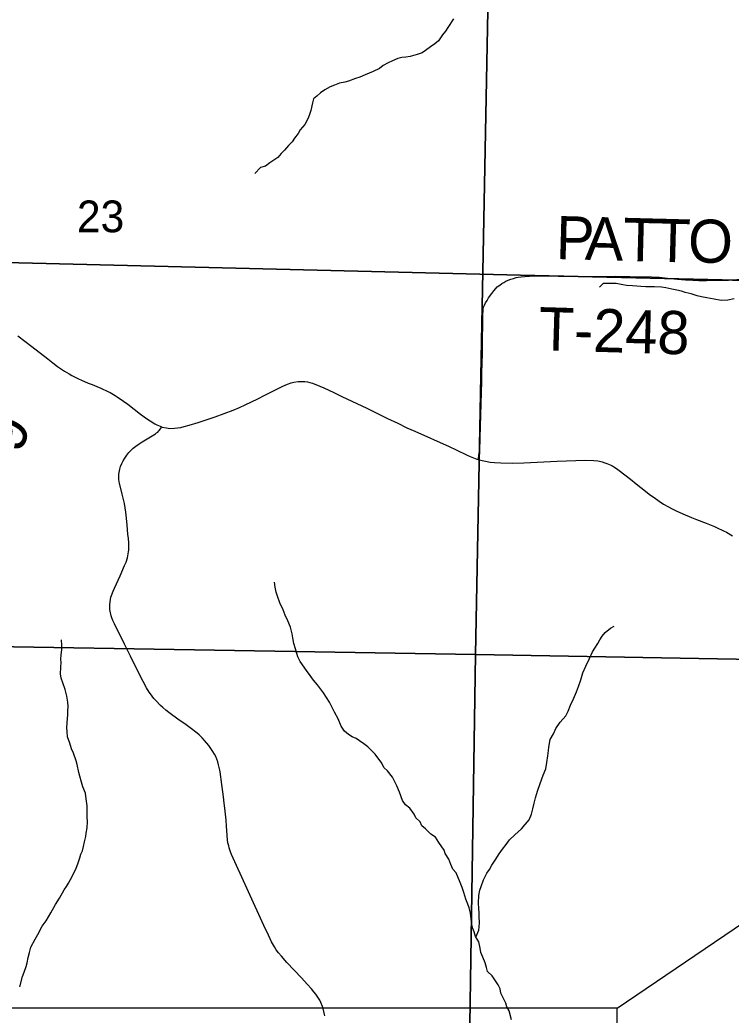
# Model space of a CAD drawing. Extents: x 0 to 34, y 0 to 22.
# Drawn here: x 11.845 to 12.781, y 16.534 to 17.845 of the extents above; entities that cross this region are included whole.
import ezdxf

# ---------------------------------------------------------------- set-up
doc = ezdxf.new("R2010")
doc.units = 0
for name, color, linetype in [('GM_X_Corporation', 7, 'Continuous'), ('GM_X_County_Road', 7, 'Continuous'), ('GM_X_Minor_River', 7, 'Continuous'), ('GM_X_Section_Text', 7, 'Continuous'), ('GM_X_Township_Road', 7, 'Continuous'), ('GM_X_Township_Road_Text', 7, 'Continuous'), ('SH_Text', 7, 'Continuous')]:
    doc.layers.add(name, color=color, linetype=linetype)

msp = doc.modelspace()

# ---------------------------------------------------------------- linework, layer by layer
at = {"layer": 'GM_X_Corporation'}
for points in [[(16.7661, 20.4), (11.5001, 20.4), (11.498, 20.2911), (11.486, 19.6423), (11.4741, 19.003), (11.4514, 17.7789), (11.4477, 17.5329), (11.8073, 17.526), (12.504, 17.5091), (12.7693, 17.5027), (12.7967, 17.502), (13.2742, 17.4966), (14.0954, 17.4811)], [(14.0954, 17.4811), (13.2742, 17.4966), (12.7967, 17.502), (12.7693, 17.5027), (12.504, 17.5091), (11.8073, 17.526), (11.4477, 17.5329), (11.0329, 17.5442), (10.9447, 17.5459), (10.9437, 17.4908), (10.9418, 17.3896), (10.9206, 16.4568), (10.9139, 16.0819), (10.9086, 15.7107), (10.9052, 15.3502), (10.897, 14.5214)]]:
    msp.add_lwpolyline(points, dxfattribs=at)
for points in [[(11.4565, 18.0343), (12.4638, 18.0185), (12.4446, 17.0089), (11.4395, 17.0255)], [(12.4638, 18.0185), (13.4723, 18.0001), (13.4493, 16.9912), (12.4446, 17.0089)], [(11.4395, 17.0255), (12.4446, 17.0089), (12.4291, 16.0062), (11.4274, 16.0262)], [(12.4446, 17.0089), (13.4493, 16.9912), (13.4336, 15.974), (12.4291, 16.0062)]]:
    msp.add_lwpolyline(points, close=True, dxfattribs=at)
at = {"layer": 'GM_X_County_Road'}
msp.add_lwpolyline([(11.8419, 17.429), (11.8603, 17.4148), (11.8813, 17.3985), (11.888, 17.3933), (11.8942, 17.3887), (11.9034, 17.3825), (11.9094, 17.3788), (11.9129, 17.3767), (11.9219, 17.3721), (11.9256, 17.3703), (11.9346, 17.3666), (11.9398, 17.3646), (11.9461, 17.362), (11.9512, 17.3598), (11.9603, 17.3557), (11.9634, 17.3541), (11.97, 17.3504), (11.9729, 17.3486), (11.9809, 17.343), (11.987, 17.3387), (11.9951, 17.3325), (12.0033, 17.3257), (12.0113, 17.32), (12.0161, 17.3169), (12.0225, 17.313), (12.025, 17.3116), (12.0295, 17.3097), (12.0311, 17.3092), (12.0321, 17.3088), (12.0376, 17.3076), (12.04, 17.3072), (12.0423, 17.307), (12.0482, 17.3072), (12.0521, 17.3075), (12.0567, 17.3083), (12.0612, 17.3093), (12.0677, 17.3111), (12.0796, 17.3147), (12.0885, 17.3176), (12.1019, 17.3224), (12.1255, 17.3312), (12.1339, 17.3345), (12.1413, 17.3378), (12.158, 17.3458), (12.1664, 17.3501), (12.1908, 17.3624), (12.1969, 17.3652), (12.2019, 17.3668), (12.2053, 17.3678), (12.2109, 17.3687), (12.2131, 17.3689), (12.22, 17.3687), (12.2233, 17.3682), (12.2264, 17.3675), (12.2298, 17.3664), (12.2395, 17.3627), (12.2447, 17.3605), (12.2579, 17.3543), (12.2688, 17.3492), (12.3017, 17.3335), (12.3146, 17.3272), (12.3289, 17.3202), (12.3422, 17.3137), (12.3543, 17.3079), (12.3648, 17.3032), (12.41, 17.2829), (12.419, 17.2786), (12.4337, 17.2716), (12.4378, 17.2698), (12.4443, 17.2673), (12.4463, 17.2666), (12.448, 17.2661), (12.4533, 17.2648), (12.458, 17.2637), (12.4639, 17.2625), (12.4695, 17.262), (12.4779, 17.2614), (12.493, 17.2611), (12.5084, 17.2614), (12.5521, 17.2637), (12.5891, 17.265), (12.6005, 17.2647), (12.6058, 17.2641), (12.6079, 17.2637), (12.6113, 17.2629), (12.6149, 17.2618), (12.6175, 17.2608), (12.6241, 17.2579), (12.6267, 17.2564), (12.6302, 17.2541), (12.6339, 17.2515), (12.6486, 17.2402), (12.6562, 17.234), (12.6623, 17.229), (12.6752, 17.219), (12.6798, 17.2157), (12.6864, 17.2111), (12.6924, 17.2072), (12.6989, 17.2035), (12.7029, 17.2013), (12.7088, 17.1983), (12.7177, 17.1943), (12.729, 17.1896), (12.7355, 17.1871), (12.7486, 17.1821), (12.7593, 17.1778), (12.7622, 17.1765), (12.7714, 17.1721), (12.775, 17.1701), (12.7831, 17.1652)], dxfattribs=at)
at = {"layer": 'GM_X_Minor_River'}
for points in [[(12.4155, 17.8467), (12.408, 17.8353), (12.405, 17.8304), (12.4012, 17.8254), (12.3959, 17.8178), (12.391, 17.8136), (12.3853, 17.8098), (12.3789, 17.8049), (12.3743, 17.8018), (12.3679, 17.7995), (12.3588, 17.7972), (12.3527, 17.7961), (12.3478, 17.7957), (12.3424, 17.7946), (12.3352, 17.7915), (12.3296, 17.7888), (12.3231, 17.785), (12.3182, 17.7812), (12.3099, 17.7774), (12.2992, 17.7729), (12.2924, 17.7698), (12.2864, 17.7679), (12.2773, 17.7645), (12.2727, 17.7633), (12.2655, 17.7618), (12.259, 17.7591)], [(12.259, 17.7591), (12.2534, 17.7572), (12.2462, 17.753), (12.2405, 17.7492), (12.2359, 17.7447), (12.2314, 17.7412), (12.2299, 17.7359), (12.228, 17.726), (12.2262, 17.7207), (12.2243, 17.7158), (12.2197, 17.7074), (12.2137, 17.7002), (12.2111, 17.6956), (12.2065, 17.6896), (12.2031, 17.6846), (12.1986, 17.6797), (12.1933, 17.6736), (12.1887, 17.669), (12.1842, 17.6641), (12.1789, 17.6603), (12.1736, 17.6568), (12.1679, 17.6527), (12.1615, 17.6508), (12.1539, 17.6428)], [(12.7851, 17.4775), (12.7771, 17.476), (12.7684, 17.4756), (12.7589, 17.4771), (12.7494, 17.4789), (12.7422, 17.4805), (12.7365, 17.4816), (12.7285, 17.4842), (12.7209, 17.4861), (12.716, 17.4876), (12.7099, 17.4891), (12.703, 17.4906), (12.6951, 17.4921), (12.6894, 17.4929), (12.6806, 17.4933), (12.6742, 17.4936), (12.6689, 17.4936), (12.6624, 17.494), (12.6571, 17.4944), (12.6514, 17.4947), (12.6434, 17.4951), (12.6385, 17.4962), (12.6301, 17.4977), (12.6248, 17.4981), (12.6187, 17.4981), (12.6127, 17.4977), (12.6081, 17.4931)], [(12.2012, 17.0452), (12.1977, 17.0535), (12.1939, 17.0607), (12.1912, 17.0679), (12.187, 17.077), (12.1839, 17.0858), (12.182, 17.0911), (12.1809, 17.0979), (12.1801, 17.1044)], [(12.4919, 16.5277), (12.4892, 16.5395), (12.4861, 16.5448), (12.4846, 16.5497), (12.4781, 16.5626), (12.4773, 16.5683), (12.4746, 16.5736), (12.4701, 16.5801), (12.4666, 16.5857), (12.4605, 16.5914), (12.459, 16.5964), (12.4575, 16.6028), (12.4544, 16.61), (12.4517, 16.6165), (12.4509, 16.6222), (12.449, 16.6305), (12.4448, 16.6374), (12.4429, 16.6434), (12.441, 16.648), (12.4398, 16.6533), (12.439, 16.6605), (12.4379, 16.6681), (12.4363, 16.6753), (12.4344, 16.6802), (12.4321, 16.6867), (12.4294, 16.6954), (12.4271, 16.7019), (12.4244, 16.7087), (12.4191, 16.7212), (12.4149, 16.7262), (12.4122, 16.7322), (12.4095, 16.7394), (12.4046, 16.7466), (12.4034, 16.7512), (12.3962, 16.7614), (12.392, 16.7683), (12.3859, 16.7721), (12.3786, 16.7793), (12.3741, 16.7831), (12.3718, 16.7884), (12.3661, 16.7937), (12.3638, 16.7986), (12.358, 16.8066), (12.3523, 16.8107), (12.3485, 16.8168), (12.3447, 16.8278), (12.3412, 16.8358), (12.3355, 16.8472), (12.3286, 16.8559), (12.3241, 16.8601), (12.3214, 16.8657), (12.3126, 16.8779), (12.3027, 16.8874), (12.2974, 16.8911), (12.2921, 16.8953), (12.2875, 16.8983), (12.2822, 16.9006), (12.2776, 16.9036), (12.2723, 16.9082), (12.2677, 16.9146), (12.2639, 16.9241), (12.2589, 16.9329), (12.2562, 16.9385), (12.2524, 16.9461), (12.2444, 16.9587), (12.2364, 16.9689), (12.2314, 16.9753), (12.2268, 16.9814), (12.2223, 16.9879), (12.2139, 17), (12.2108, 17.0061), (12.2077, 17.0163), (12.2054, 17.0235), (12.2043, 17.0311), (12.2031, 17.0364), (12.2012, 17.0452)], [(12.4452, 16.6367), (12.449, 16.6457), (12.4497, 16.6503), (12.4501, 16.6556), (12.4497, 16.6636), (12.4493, 16.6689), (12.4489, 16.6738), (12.4488, 16.6818), (12.4492, 16.6913), (12.4503, 16.6985), (12.4522, 16.7034), (12.4552, 16.7122), (12.4597, 16.7209), (12.4631, 16.7259), (12.4661, 16.7312), (12.4707, 16.738), (12.4759, 16.7464), (12.4801, 16.7525), (12.485, 16.7585), (12.4895, 16.7646), (12.4964, 16.7715), (12.5009, 16.7753), (12.5054, 16.7795), (12.51, 16.7848), (12.5153, 16.7913), (12.5183, 16.7985), (12.5202, 16.8057), (12.5217, 16.8133), (12.5235, 16.8201), (12.5262, 16.8289), (12.5299, 16.8391), (12.5337, 16.8501), (12.5371, 16.8585), (12.5386, 16.8665), (12.5397, 16.8756), (12.5408, 16.8824), (12.5411, 16.887), (12.543, 16.8972), (12.5475, 16.9045), (12.5505, 16.9117), (12.5562, 16.92), (12.5634, 16.9284), (12.5668, 16.9345), (12.5698, 16.9421), (12.5736, 16.9505), (12.5777, 16.96), (12.5803, 16.9668), (12.5834, 16.9755), (12.586, 16.985), (12.5901, 16.9938), (12.5946, 17.0037), (12.5988, 17.0124), (12.6018, 17.0173), (12.6056, 17.0234), (12.6082, 17.0284), (12.6116, 17.0333), (12.6154, 17.0379), (12.6226, 17.0439), (12.6271, 17.0462)], [(11.8542, 16.6027), (11.8557, 16.6099), (11.8572, 16.6164), (11.8591, 16.6232), (11.8647, 16.6338), (11.8681, 16.6399), (11.8741, 16.6509), (11.8791, 16.6582), (11.8821, 16.6635), (11.8855, 16.6688), (11.8915, 16.6794), (11.8968, 16.6878), (11.9028, 16.6988), (11.9062, 16.7034), (11.9085, 16.7079), (11.9111, 16.7125), (11.9157, 16.7209), (11.9187, 16.7273), (11.9209, 16.733), (11.9236, 16.741), (11.9251, 16.7459), (11.9269, 16.7505), (11.9284, 16.7562), (11.9299, 16.7623), (11.9314, 16.7691), (11.9318, 16.7737), (11.9333, 16.7805), (11.9337, 16.7885), (11.9332, 16.7953), (11.9332, 16.8094), (11.932, 16.8189), (11.9309, 16.8261), (11.9274, 16.8348), (11.9259, 16.8409), (11.9236, 16.8485), (11.9224, 16.8534), (11.9201, 16.864), (11.9189, 16.869), (11.9151, 16.8792), (11.9128, 16.8849), (11.9105, 16.8921), (11.9074, 16.9005), (11.9067, 16.9077), (11.9066, 16.9126), (11.907, 16.9191), (11.9074, 16.9248), (11.9077, 16.9297), (11.9077, 16.9346), (11.9081, 16.9407), (11.9077, 16.9464), (11.9065, 16.954), (11.9042, 16.9631), (11.9011, 16.9718), (11.8992, 16.9779), (11.898, 16.9836), (11.8984, 16.9923), (11.8988, 16.9984), (11.8987, 17.003), (11.8991, 17.0083), (11.8998, 17.0155), (11.8998, 17.0212), (11.8994, 17.0284)], [(11.8444, 16.5712), (11.8482, 16.5848), (11.8504, 16.5905), (11.8527, 16.5981), (11.8542, 16.6027)]]:
    msp.add_lwpolyline(points, dxfattribs=at)
at = {"layer": 'GM_X_Township_Road'}
for points in [[(12.448, 17.2661), (12.4485, 17.2679), (12.4496, 17.2745), (12.4498, 17.277), (12.4507, 17.2889), (12.4509, 17.2944), (12.4525, 17.3542), (12.4529, 17.3682), (12.4532, 17.3801), (12.4537, 17.4055), (12.454, 17.4213), (12.4541, 17.4475), (12.4543, 17.4575), (12.4546, 17.4613), (12.4548, 17.464), (12.4554, 17.4665), (12.4564, 17.4692), (12.4579, 17.4725), (12.46, 17.4757), (12.4619, 17.4788), (12.4663, 17.4849), (12.4688, 17.4883), (12.4714, 17.4914), (12.4734, 17.4933), (12.4765, 17.4958), (12.4794, 17.4979), (12.4819, 17.4994), (12.4847, 17.5009), (12.4878, 17.5023), (12.491, 17.5036), (12.4945, 17.5047), (12.498, 17.5056), (12.5007, 17.5062), (12.505, 17.5067), (12.5096, 17.5072), (12.5134, 17.5076), (12.5158, 17.5077), (12.5189, 17.508)], [(12.5189, 17.508), (12.525, 17.5079), (12.5351, 17.5079), (12.5535, 17.5075), (12.5747, 17.5073), (12.6286, 17.5074), (12.6403, 17.5073), (12.6478, 17.5072), (12.6763, 17.5069), (12.6865, 17.5062)], [(12.6865, 17.5062), (12.6936, 17.5054), (12.7018, 17.5046), (12.7108, 17.5037), (12.7211, 17.5028), (12.7309, 17.5022), (12.7389, 17.5019), (12.7487, 17.5018), (12.7687, 17.5021), (12.7779, 17.5025), (12.7886, 17.5032), (12.7955, 17.5041), (12.8007, 17.5049), (12.8017, 17.5051)], [(12.2464, 16.5327), (12.246, 16.5348), (12.2451, 16.5385), (12.2441, 16.5424), (12.2432, 16.545), (12.2409, 16.5506), (12.2396, 16.5533), (12.238, 16.5561), (12.2345, 16.5615), (12.2319, 16.5644), (12.2287, 16.5683), (12.2231, 16.5745), (12.2153, 16.5829), (12.2057, 16.5931), (12.1964, 16.6032), (12.189, 16.6115), (12.1852, 16.616), (12.1822, 16.62), (12.1798, 16.6238), (12.1761, 16.6302), (12.1741, 16.6343), (12.1719, 16.639), (12.1661, 16.6519), (12.1234, 16.7456), (12.122, 16.7492), (12.1202, 16.7543), (12.1196, 16.7567), (12.1187, 16.761), (12.1179, 16.7647), (12.1166, 16.7828), (12.1162, 16.7906), (12.1145, 16.8065), (12.1137, 16.8131), (12.1127, 16.8213), (12.1106, 16.8378), (12.1084, 16.8543), (12.1079, 16.8568), (12.1063, 16.8637), (12.1051, 16.8675), (12.1039, 16.8712), (12.1025, 16.8746), (12.1009, 16.8777), (12.0987, 16.8814), (12.0962, 16.8852), (12.0934, 16.889), (12.0877, 16.8959), (12.0846, 16.8993), (12.0808, 16.903), (12.0782, 16.9053), (12.0688, 16.9124), (12.0618, 16.9175), (12.0546, 16.9227), (12.0409, 16.9324), (12.0369, 16.9356), (12.0329, 16.939), (12.0299, 16.9418), (12.0235, 16.9485), (12.0212, 16.9511), (12.0166, 16.957), (12.0149, 16.9596), (12.0115, 16.9653), (12.007, 16.9736), (11.9988, 16.9897), (11.9903, 17.0067), (11.9824, 17.0226), (11.9691, 17.0495), (11.967, 17.054), (11.9658, 17.0572), (11.9649, 17.0601), (11.9635, 17.066), (11.9632, 17.0684), (11.9629, 17.0731), (11.963, 17.0751), (11.9639, 17.0816), (11.9645, 17.0844), (11.9651, 17.0866), (11.9673, 17.0924), (11.9691, 17.0965), (11.9765, 17.1126), (11.9826, 17.1262), (11.9844, 17.1307), (11.9862, 17.1363), (11.9868, 17.1391), (11.9877, 17.1442), (11.988, 17.1467), (11.988, 17.1495), (11.9881, 17.1521), (11.9879, 17.1562), (11.9875, 17.1617), (11.987, 17.1674), (11.9858, 17.1795), (11.9851, 17.1885), (11.9842, 17.1964), (11.9834, 17.2024), (11.9824, 17.2078), (11.9808, 17.2152), (11.9795, 17.2204), (11.9757, 17.2346), (11.9753, 17.2367), (11.975, 17.2399), (11.9749, 17.2436), (11.975, 17.2465), (11.9756, 17.2512), (11.9761, 17.2532), (11.9772, 17.2566), (11.9787, 17.2605), (11.9807, 17.2642), (11.9827, 17.2676), (11.9854, 17.2716), (11.9882, 17.2753), (11.9907, 17.2779), (11.9938, 17.281), (11.9972, 17.2837), (12.0016, 17.2868), (12.0057, 17.2894), (12.0231, 17.2998), (12.0246, 17.3009), (12.0263, 17.3021), (12.0278, 17.3037), (12.0285, 17.3047), (12.0305, 17.3079), (12.0311, 17.3092)]]:
    msp.add_lwpolyline(points, dxfattribs=at)
at = {"layer": 'SH_Text'}
msp.add_line((12.6312, 16.5428), (13.1827, 16.9178), dxfattribs=at)
msp.add_lwpolyline([(11.3701, 16.5428), (11.3701, 16.3028), (12.6312, 16.3028), (12.6312, 16.5428)], close=True, dxfattribs=at)

# ---------------------------------------------------------------- texts
at = {"layer": 'GM_X_Section_Text'}
msp.add_text('23', height=0.04186, rotation=0, dxfattribs=at).set_placement((11.9198, 17.5654))
at = {"layer": 'GM_X_Township_Road_Text'}
for s, height, rotation, p in [('P', 0.0568, 358.4556, (12.55, 17.5302)), ('A', 0.0568, 358.4593, (12.5883, 17.5292)), ('T', 0.0568, 358.4571, (12.6383, 17.5278)), ('T', 0.0568, 358.4612, (12.6808, 17.5267)), ('O', 0.0568, 359.5044, (12.7244, 17.5255)), ('T-248', 0.05682, 358.3152, (12.5273, 17.4101)), ('9', 0.0568, 69.6112, (11.8455, 17.2725))]:
    msp.add_text(s, height=height, rotation=rotation, dxfattribs=at).set_placement(p)

doc.saveas('drawing.dxf')
